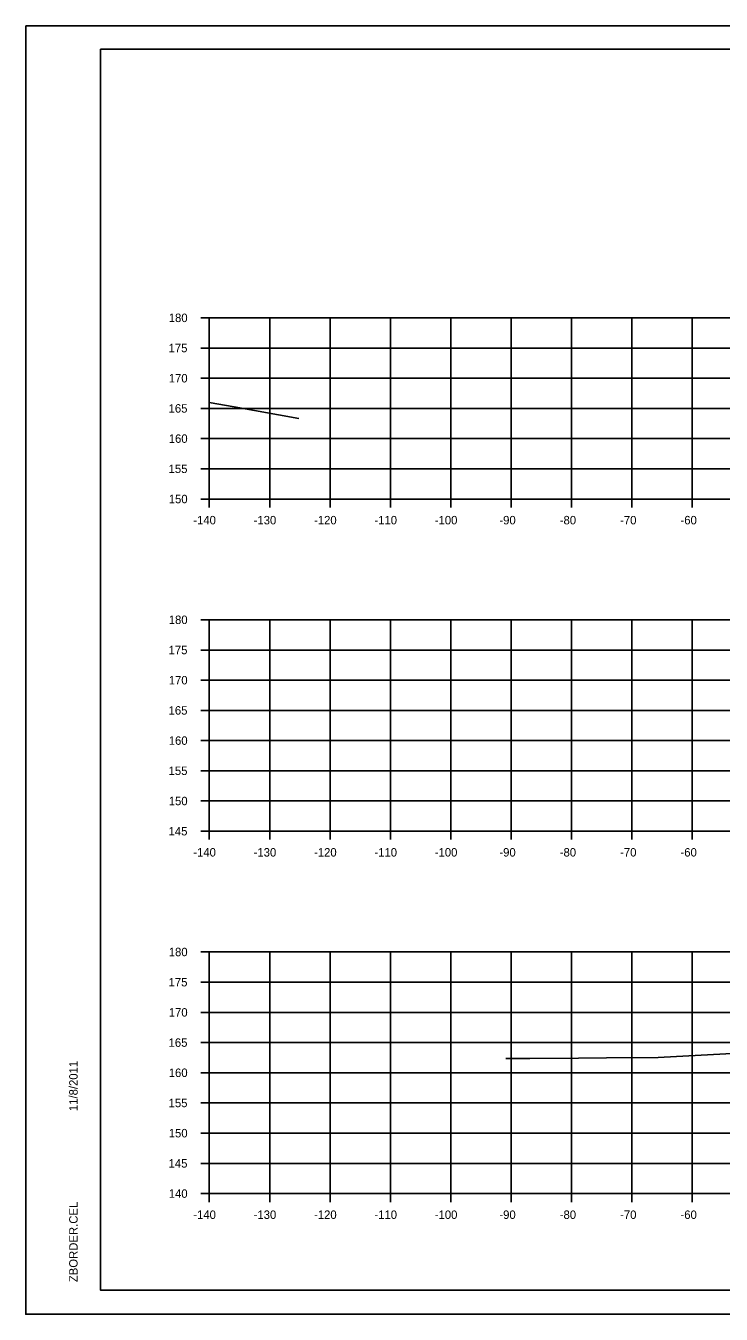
# Model space of a CAD drawing. Extents: x 1368503 to 1373085, y 379840 to 381833.
# Drawn here: x 1372751.7 to 1372866.9, y 380815 to 381028.3 of the extents above; entities that cross this region are included whole.
import ezdxf

# ---------------------------------------------------------------- set-up
doc = ezdxf.new("R2010")
doc.units = 0
for name, color, linetype in [('S_BRIDGE', 7, 'Continuous'), ('S_EDGE_PAVEMENT', 7, 'Continuous'), ('S_MISC_BOUNDARY', 7, 'Continuous'), ('S_PHOTO_CENTERS', 7, 'Continuous'), ('S_PHOTO_NOTES', 7, 'Continuous'), ('S_TRAILS', 7, 'Continuous')]:
    doc.layers.add(name, color=color, linetype=linetype)

msp = doc.modelspace()

# ---------------------------------------------------------------- linework, layer by layer
at = {"layer": 'S_BRIDGE'}
for p, q in [((1372764.08, 381024.42), (1373080.26, 381024.42)), ((1372764.08, 380818.96), (1372764.08, 381024.42)), ((1372764.08, 380818.96), (1372764.08, 380818.96)), ((1373080.26, 380818.96), (1372764.08, 380818.96))]:
    msp.add_line(p, q, dxfattribs=at)
at = {"layer": 'S_EDGE_PAVEMENT'}
for p, q in [((1372780.68, 380979.96), (1372782.08, 380979.96)), ((1372782.08, 380949.96), (1372782.08, 380979.96)), ((1372780.68, 380974.96), (1372782.08, 380974.96)), ((1372780.68, 380969.96), (1372782.08, 380969.96)), ((1372780.68, 380964.96), (1372782.08, 380964.96)), ((1372780.68, 380959.96), (1372782.08, 380959.96)), ((1372780.68, 380954.96), (1372782.08, 380954.96)), ((1372780.68, 380949.96), (1372782.08, 380949.96)), ((1372782.08, 380949.96), (1373062.08, 380949.96)), ((1372782.08, 380948.56), (1372782.08, 380949.96)), ((1372792.08, 380948.56), (1372792.08, 380949.96)), ((1372802.08, 380948.56), (1372802.08, 380949.96)), ((1372812.08, 380948.56), (1372812.08, 380949.96)), ((1372822.08, 380948.56), (1372822.08, 380949.96)), ((1372832.08, 380948.56), (1372832.08, 380949.96)), ((1372842.08, 380948.56), (1372842.08, 380949.96)), ((1372852.08, 380948.56), (1372852.08, 380949.96)), ((1372862.08, 380948.56), (1372862.08, 380949.96)), ((1372780.68, 380929.96), (1372782.08, 380929.96)), ((1372782.08, 380894.96), (1372782.08, 380929.96)), ((1372780.68, 380924.96), (1372782.08, 380924.96)), ((1372780.68, 380919.96), (1372782.08, 380919.96)), ((1372780.68, 380914.96), (1372782.08, 380914.96)), ((1372780.68, 380909.96), (1372782.08, 380909.96)), ((1372780.68, 380904.96), (1372782.08, 380904.96)), ((1372780.68, 380899.96), (1372782.08, 380899.96)), ((1372780.68, 380894.96), (1372782.08, 380894.96)), ((1372782.08, 380894.96), (1373062.08, 380894.96)), ((1372782.08, 380893.56), (1372782.08, 380894.96)), ((1372792.08, 380893.56), (1372792.08, 380894.96)), ((1372802.08, 380893.56), (1372802.08, 380894.96)), ((1372812.08, 380893.56), (1372812.08, 380894.96)), ((1372822.08, 380893.56), (1372822.08, 380894.96)), ((1372832.08, 380893.56), (1372832.08, 380894.96)), ((1372842.08, 380893.56), (1372842.08, 380894.96)), ((1372852.08, 380893.56), (1372852.08, 380894.96)), ((1372862.08, 380893.56), (1372862.08, 380894.96)), ((1372780.68, 380874.96), (1372782.08, 380874.96)), ((1372782.08, 380834.96), (1372782.08, 380874.96)), ((1372780.68, 380869.96), (1372782.08, 380869.96)), ((1372780.68, 380864.96), (1372782.08, 380864.96)), ((1372780.68, 380859.96), (1372782.08, 380859.96)), ((1372780.68, 380854.96), (1372782.08, 380854.96)), ((1372780.68, 380849.96), (1372782.08, 380849.96)), ((1372780.68, 380844.96), (1372782.08, 380844.96)), ((1372780.68, 380839.96), (1372782.08, 380839.96)), ((1372780.68, 380834.96), (1372782.08, 380834.96)), ((1372782.08, 380834.96), (1373062.08, 380834.96)), ((1372782.08, 380833.56), (1372782.08, 380834.96)), ((1372792.08, 380833.56), (1372792.08, 380834.96)), ((1372802.08, 380833.56), (1372802.08, 380834.96)), ((1372812.08, 380833.56), (1372812.08, 380834.96)), ((1372822.08, 380833.56), (1372822.08, 380834.96)), ((1372832.08, 380833.56), (1372832.08, 380834.96)), ((1372842.08, 380833.56), (1372842.08, 380834.96)), ((1372852.08, 380833.56), (1372852.08, 380834.96)), ((1372862.08, 380833.56), (1372862.08, 380834.96))]:
    msp.add_line(p, q, dxfattribs=at)
at = {"layer": 'S_MISC_BOUNDARY'}
for points in [[(1372782.08, 380965.96), (1372786.19, 380965.24), (1372796.88, 380963.3)], [(1372831.18, 380857.3), (1372835.19, 380857.32), (1372843.25, 380857.37), (1372847.87, 380857.42), (1372856.45, 380857.48), (1372896.24, 380859.65)]]:
    msp.add_lwpolyline(points, dxfattribs=at)
at = {"layer": 'S_PHOTO_CENTERS'}
for p, q in [((1372782.08, 380979.96), (1373062.08, 380979.96)), ((1372782.08, 380949.96), (1372782.08, 380979.96)), ((1372782.08, 380979.96), (1373062.08, 380979.96)), ((1372782.08, 380949.96), (1372782.08, 380979.96)), ((1372792.08, 380949.96), (1372792.08, 380979.96)), ((1372792.08, 380949.96), (1372792.08, 380979.96)), ((1372802.08, 380949.96), (1372802.08, 380979.96)), ((1372802.08, 380949.96), (1372802.08, 380979.96)), ((1372812.08, 380949.96), (1372812.08, 380979.96)), ((1372812.08, 380949.96), (1372812.08, 380979.96)), ((1372822.08, 380949.96), (1372822.08, 380979.96)), ((1372822.08, 380949.96), (1372822.08, 380979.96)), ((1372832.08, 380949.96), (1372832.08, 380979.96)), ((1372832.08, 380949.96), (1372832.08, 380979.96)), ((1372842.08, 380949.96), (1372842.08, 380979.96)), ((1372842.08, 380949.96), (1372842.08, 380979.96)), ((1372852.08, 380949.96), (1372852.08, 380979.96)), ((1372852.08, 380949.96), (1372852.08, 380979.96)), ((1372862.08, 380949.96), (1372862.08, 380979.96)), ((1372862.08, 380949.96), (1372862.08, 380979.96)), ((1372782.08, 380974.96), (1373062.08, 380974.96)), ((1372782.08, 380974.96), (1373062.08, 380974.96)), ((1372782.08, 380969.96), (1373062.08, 380969.96)), ((1372782.08, 380969.96), (1373062.08, 380969.96)), ((1372782.08, 380964.96), (1373062.08, 380964.96)), ((1372782.08, 380964.96), (1373062.08, 380964.96)), ((1372782.08, 380959.96), (1373062.08, 380959.96)), ((1372782.08, 380959.96), (1373062.08, 380959.96)), ((1372782.08, 380954.96), (1373062.08, 380954.96)), ((1372782.08, 380954.96), (1373062.08, 380954.96)), ((1372782.08, 380949.96), (1373062.08, 380949.96)), ((1372782.08, 380949.96), (1373062.08, 380949.96)), ((1372782.08, 380929.96), (1373062.08, 380929.96)), ((1372782.08, 380894.96), (1372782.08, 380929.96)), ((1372792.08, 380894.96), (1372792.08, 380929.96)), ((1372802.08, 380894.96), (1372802.08, 380929.96)), ((1372812.08, 380894.96), (1372812.08, 380929.96)), ((1372822.08, 380894.96), (1372822.08, 380929.96)), ((1372832.08, 380894.96), (1372832.08, 380929.96)), ((1372842.08, 380894.96), (1372842.08, 380929.96)), ((1372852.08, 380894.96), (1372852.08, 380929.96)), ((1372862.08, 380894.96), (1372862.08, 380929.96)), ((1372782.08, 380924.96), (1373062.08, 380924.96)), ((1372782.08, 380919.96), (1373062.08, 380919.96)), ((1372782.08, 380914.96), (1373062.08, 380914.96)), ((1372782.08, 380909.96), (1373062.08, 380909.96)), ((1372782.08, 380904.96), (1373062.08, 380904.96)), ((1372782.08, 380899.96), (1373062.08, 380899.96)), ((1372782.08, 380894.96), (1373062.08, 380894.96)), ((1372782.08, 380874.96), (1373062.08, 380874.96)), ((1372782.08, 380834.96), (1372782.08, 380874.96)), ((1372792.08, 380834.96), (1372792.08, 380874.96)), ((1372802.08, 380834.96), (1372802.08, 380874.96)), ((1372812.08, 380834.96), (1372812.08, 380874.96)), ((1372822.08, 380834.96), (1372822.08, 380874.96)), ((1372832.08, 380834.96), (1372832.08, 380874.96)), ((1372842.08, 380834.96), (1372842.08, 380874.96)), ((1372852.08, 380834.96), (1372852.08, 380874.96)), ((1372862.08, 380834.96), (1372862.08, 380874.96)), ((1372782.08, 380869.96), (1373062.08, 380869.96)), ((1372782.08, 380864.96), (1373062.08, 380864.96)), ((1372782.08, 380859.96), (1373062.08, 380859.96)), ((1372782.08, 380854.96), (1373062.08, 380854.96)), ((1372782.08, 380849.96), (1373062.08, 380849.96)), ((1372782.08, 380844.96), (1373062.08, 380844.96)), ((1372782.08, 380839.96), (1373062.08, 380839.96)), ((1372782.08, 380834.96), (1373062.08, 380834.96))]:
    msp.add_line(p, q, dxfattribs=at)
at = {"layer": 'S_PHOTO_NOTES'}
for p, q in [((1372751.68, 381028.32), (1373085.01, 381028.32)), ((1372751.68, 380814.98), (1373085.01, 380814.98))]:
    msp.add_line(p, q, dxfattribs=at)
for points in [[(1372751.67, 381028.32), (1373085.01, 381028.32), (1373085.01, 380814.98), (1372751.67, 380814.98)], [(1372998, 381024.42), (1372998, 381014.54), (1373033.73, 381014.54), (1373033.73, 381011.62), (1373056.93, 381011.62), (1373056.93, 380987.29), (1373080.26, 380987.29), (1373080.26, 380818.96), (1372764.08, 380818.96), (1372764.08, 381024.42)]]:
    msp.add_lwpolyline(points, close=True, dxfattribs=at)

# ---------------------------------------------------------------- texts
at = {"layer": 'S_BRIDGE'}
for s, p in [('11/8/2011', (1372760.27, 380848.61)), ('ZBORDER.CEL', (1372760.27, 380820.29))]:
    msp.add_text(s, height=1.4, rotation=90, dxfattribs=at).set_placement(p)
at = {"layer": 'S_TRAILS'}
for s, p in [('180', (1372775.36, 380979.26)), ('175', (1372775.33, 380974.26)), ('170', (1372775.36, 380969.26)), ('165', (1372775.33, 380964.26)), ('160', (1372775.36, 380959.26)), ('155', (1372775.33, 380954.26)), ('150', (1372775.36, 380949.26)), ('-140', (1372779.42, 380945.76)), ('-130', (1372789.42, 380945.76)), ('-120', (1372799.42, 380945.76)), ('-110', (1372809.42, 380945.76)), ('-100', (1372819.42, 380945.76)), ('-90', (1372830.12, 380945.76)), ('-80', (1372840.12, 380945.76)), ('-70', (1372850.12, 380945.76)), ('-60', (1372860.12, 380945.76)), ('180', (1372775.36, 380929.26)), ('175', (1372775.33, 380924.26)), ('170', (1372775.36, 380919.26)), ('165', (1372775.33, 380914.26)), ('160', (1372775.36, 380909.26)), ('155', (1372775.33, 380904.26)), ('150', (1372775.36, 380899.26)), ('145', (1372775.33, 380894.26)), ('-140', (1372779.42, 380890.76)), ('-130', (1372789.42, 380890.76)), ('-120', (1372799.42, 380890.76)), ('-110', (1372809.42, 380890.76)), ('-100', (1372819.42, 380890.76)), ('-90', (1372830.12, 380890.76)), ('-80', (1372840.12, 380890.76)), ('-70', (1372850.12, 380890.76)), ('-60', (1372860.12, 380890.76)), ('180', (1372775.36, 380874.26)), ('175', (1372775.33, 380869.26)), ('170', (1372775.36, 380864.26)), ('165', (1372775.33, 380859.26)), ('160', (1372775.36, 380854.26)), ('155', (1372775.33, 380849.26)), ('150', (1372775.36, 380844.26)), ('145', (1372775.33, 380839.26)), ('140', (1372775.36, 380834.26)), ('-140', (1372779.42, 380830.76)), ('-130', (1372789.42, 380830.76)), ('-120', (1372799.42, 380830.76)), ('-110', (1372809.42, 380830.76)), ('-100', (1372819.42, 380830.76)), ('-90', (1372830.12, 380830.76)), ('-80', (1372840.12, 380830.76)), ('-70', (1372850.12, 380830.76)), ('-60', (1372860.12, 380830.76))]:
    msp.add_text(s, height=1.4, dxfattribs=at).set_placement(p)

doc.saveas('drawing.dxf')
